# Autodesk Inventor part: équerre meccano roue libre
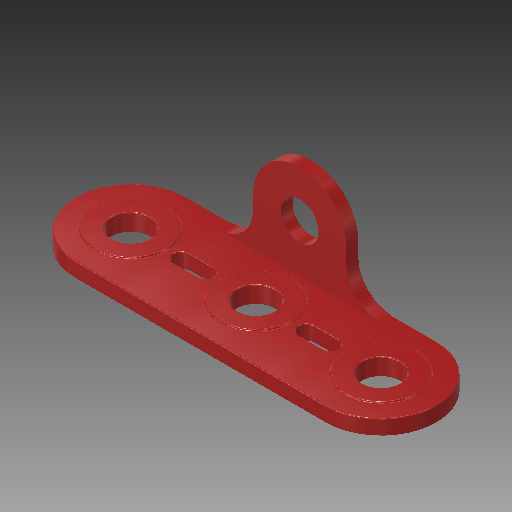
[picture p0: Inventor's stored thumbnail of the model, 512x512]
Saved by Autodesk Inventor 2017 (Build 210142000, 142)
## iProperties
Part Number: équerre meccano roue libre
Material: Plastique ABS
Document SubType Name: Modeling
Designer: ficho
Density: 1.06 g/cm^3
Appearance: Rouge
Mass: 10.1861 g
Surface Area: 66.3955 cm^2
Volume: 9.60956 cm^3
Author: ficho
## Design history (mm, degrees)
sketch "Esquisse2"
  geometry: L1 (-20, 20)-(20, 20); L2 (20, 20)-(20, -20); L3 (20, -20)-(-20, -20); L4 (-20, -20)-(-20, 20); 1 further point
  constraints: 8 end point, 2 parallel, 1 horizontal, 1 perpendicular
  dimensions: "d0" = 20 distance from line of point (0, 0) L4; "d1" = 40 distance between parallel lines of L2 L4 (= 2 x d0); "d2" = 20 distance from line of point (0, 0) L1 (= d0); "d3" = 40 distance between parallel lines of L3 L1 (= d1)
extrude "Extrusion1" new body sketch "Esquisse2" distance "d4" = 3; taper "d5" = 0 deg
sketch "Esquisse3"
  geometry: L1 (20, 20)-(-20, 20) reference; L2 (-20, 20)-(-20, -20) reference; L3 (-20, -20)-(20, -20) reference; L4 (20, -20)-(20, 20) reference; L5 (20, -20)-(20, 20) reference; L6 (-20, -20)-(20, -20); L7 (20, -20)-(20, -17); L8 (20, -17)-(-20, -17); L9 (-20, -17)-(-20, -20); 1 further point
  constraints: 8 end point, 2 parallel, 1 horizontal, 1 perpendicular, 1 point on line
  dimensions: "d6" = 3 distance of L7.end L6.end
extrude "Extrusion2" join sketch "Esquisse3" distance "d7" = 17; taper "d8" = 0 deg
sketch "Esquisse4"
  geometry: L1 (-20, -20)-(20, -20) reference; C1 r 4.75 at (0, -5); 1 further point
  constraints: 1 centre point
  dimensions: "d9" = 9.5 diameter of C1; "d10" = 15 distance from line of L1 C1.centre
extrude "Extrusion3" cut sketch "Esquisse4" stored distance "d11" = 17; taper "d12" = 0 deg
sketch "Esquisse6"
  geometry: L1 (-20, -20)-(20, -20) reference; L2 (20, -20)-(20, -17) reference; L3 (20, -17)-(-20, -17) reference; L4 (-20, -17)-(-20, -20) reference; 1 further point
extrude "Extrusion4" cut sketch "Esquisse6" stored distance "d27" = 10; taper "d28" = 0 deg
sketch "Esquisse7"
  geometry: L1 (40, -3)-(0, -3) reference; L2 (-11.5, 25)-(51.5, 25); L3 (51.5, -3)-(-11.5, -3); C1 r 4.75 at (20, 11); C2 r 4.75 at (51.5, 11); C3 r 4.75 at (-11.5, 11); A1 r 14 centre (51.5, 11) between (51.5, -3) and (51.5, 25); A2 r 14 centre (-11.5, 11) between (-11.5, 25) and (-11.5, -3); 1 further point
  constraints: 5 centre point, 4 end point, 4 point on circle, 3 tangent, 2 coincident, 1 point on line
  dimensions: "d29" = 9.5 diameter of C1 (= d30); "d30" = 9.5 diameter of C2; "d31" = 9.5 diameter of C3 (= d29); "d32" = 14 distance from line of L1 C2.centre; "d33" = 14 distance from line of L1 C1.centre (= d32); "d34" = 14 distance from line of C3.centre L1 (= d32); "d35" = 31.5 distance of C2.centre C1.centre; "d36" = 31.5 distance of C3.centre C1.centre (= d35)
extrude "Extrusion5" join sketch "Esquisse7" distance "d37" = 3.8; taper "d38" = 0 deg
fillet "Congé1" dims "d39" = 0.25
fillet "Congé2" dims "d40" = 12
sketch "Esquisse8"
  geometry: L1 (38.75, -9)-(32.75, -9); L2 (32.75, -13)-(38.75, -13); L3 (-11.5, -25)-(51.5, -25) reference; L4 (51.5, -24.75)-(-11.5, -24.75) reference; C1 r 4.75 at (51.5, -11) reference; C2 r 4.75 at (20, -11) reference; A1 r 2 centre (32.75, -11) between (32.75, -9) and (32.75, -13); A2 r 2 centre (38.75, -11) between (38.75, -13) and (38.75, -9); 1 further point
  constraints: 4 end point, 4 point on circle, 4 tangent, 2 centre point, 1 parallel
  dimensions: "d41" = 4 diameter of A1; "d42" = 4 diameter of A2 (= d41); "d43" = 6 distance of A2.centre A1.centre; "d47" = 12 distance between parallel lines of L3 L2; "d48" = 12.75 distance of A2.centre C1.centre
extrude "Extrusion6" cut sketch "Esquisse8" stored distance "d57" = 3.8; taper "d58" = 0 deg
fillet "Congé3" dims "d59" = 0.25
pattern_linear "Réseau rectangulaire1" dims "d62" = 31.5
sketch "Esquisse9"
  geometry: L1 (32.75, -13.25)-(38.75, -13.25) reference; L2 (38.75, -8.75)-(32.75, -8.75) reference; L3 (-0.25, 2.75)-(-0.25, 0.25) reference; L4 (-11.5, 2.75)-(-0.25, 2.75) reference; L5 (51.5, -24.75)-(-11.5, -24.75) reference; L6 (40.25, 2.75)-(51.5, 2.75) reference; L7 (40.25, 0.25)-(40.25, 2.75) reference; L8 (0.183, 0)-(39.817, 0) reference; L9 (1.25, -13.25)-(7.25, -13.25) reference; L10 (7.25, -8.75)-(1.25, -8.75) reference; C1 r 4.75 at (51.5, -11) reference; C2 r 4.75 at (-11.5, -11) reference; C3 r 4.75 at (51.5, -11) reference; C4 r 4.75 at (20, -11) reference; C5 r 4.75 at (20, -11) reference; C6 r 9.15 at (51.5, -11); C7 r 9.15 at (20, -11); C8 r 9.15 at (-11.5, -11); A1 r 2.25 centre (38.75, -11) between (38.75, -13.25) and (38.75, -8.75) reference; A2 r 2.25 centre (32.75, -11) between (32.75, -8.75) and (32.75, -13.25) reference; A3 r 13.75 centre (-11.5, -11) between (-11.5, 2.75) and (-11.5, -24.75) reference; A4 r 13.75 centre (51.5, -11) between (51.5, -24.75) and (51.5, 2.75) reference; A5 r 2.25 centre (7.25, -11) between (7.25, -13.25) and (7.25, -8.75) reference; A6 r 2.25 centre (1.25, -11) between (1.25, -8.75) and (1.25, -13.25) reference; 1 further point
  constraints: 3 centre point, 3 coincident, 2 other
  dimensions: "d63" = 18.3 diameter of C6; "d64" = 18.3 diameter of C7; "d65" = 18.3 diameter of C8
extrude "Extrusion7" join sketch "Esquisse9" distance "d66" = 0.25; taper "d67" = 0 deg
fillet "Congé4" dims "d68" = 0.25
fillet "Congé5" dims "d69" = 0.25
node "Plan de construction1"
mirror "Symétrie1"
sketch "Esquisse10"
  geometry: L1 (-31.5, -17.25)-(-20.25, -17.25) reference; L2 (20.25, -17.25)-(31.5, -17.25) reference; L3 (-20.25, -17)-(-31.5, -17) reference; L4 (31.5, -17)-(20.25, -17) reference; L5 (-11.75, -8.5)-(-11.75, -5); L6 (11.75, -8.5)-(11.75, -5); L7 (-20.25, -17)-(-20.25, 24.17); L8 (-20.25, 24.17)-(20.25, 24.17); L9 (20.25, 24.17)-(20.25, -17); C1 r 4.75 at (0, -5) reference; A1 r 11.75 centre (0, -5) between (11.75, -5) and (-11.75, -5); A2 r 8.5 centre (-20.25, -8.5) between (-20.25, -17) and (-11.75, -8.5); A3 r 8.5 centre (20.25, -8.5) between (11.75, -8.5) and (20.25, -17); 1 further point
  constraints: 11 end point, 6 point on circle, 6 tangent, 3 centre point, 2 perpendicular, 1 coincident, 1 vertical
extrude "Extrusion8" cut sketch "Esquisse10" distance "d72" = 10; taper "d73" = 0 deg
node "Solide1"
node "Boucle projetée1"
node "Boucle projetée2"
node "Boucle projetée3"
other parameters: "d70" = -1.9
